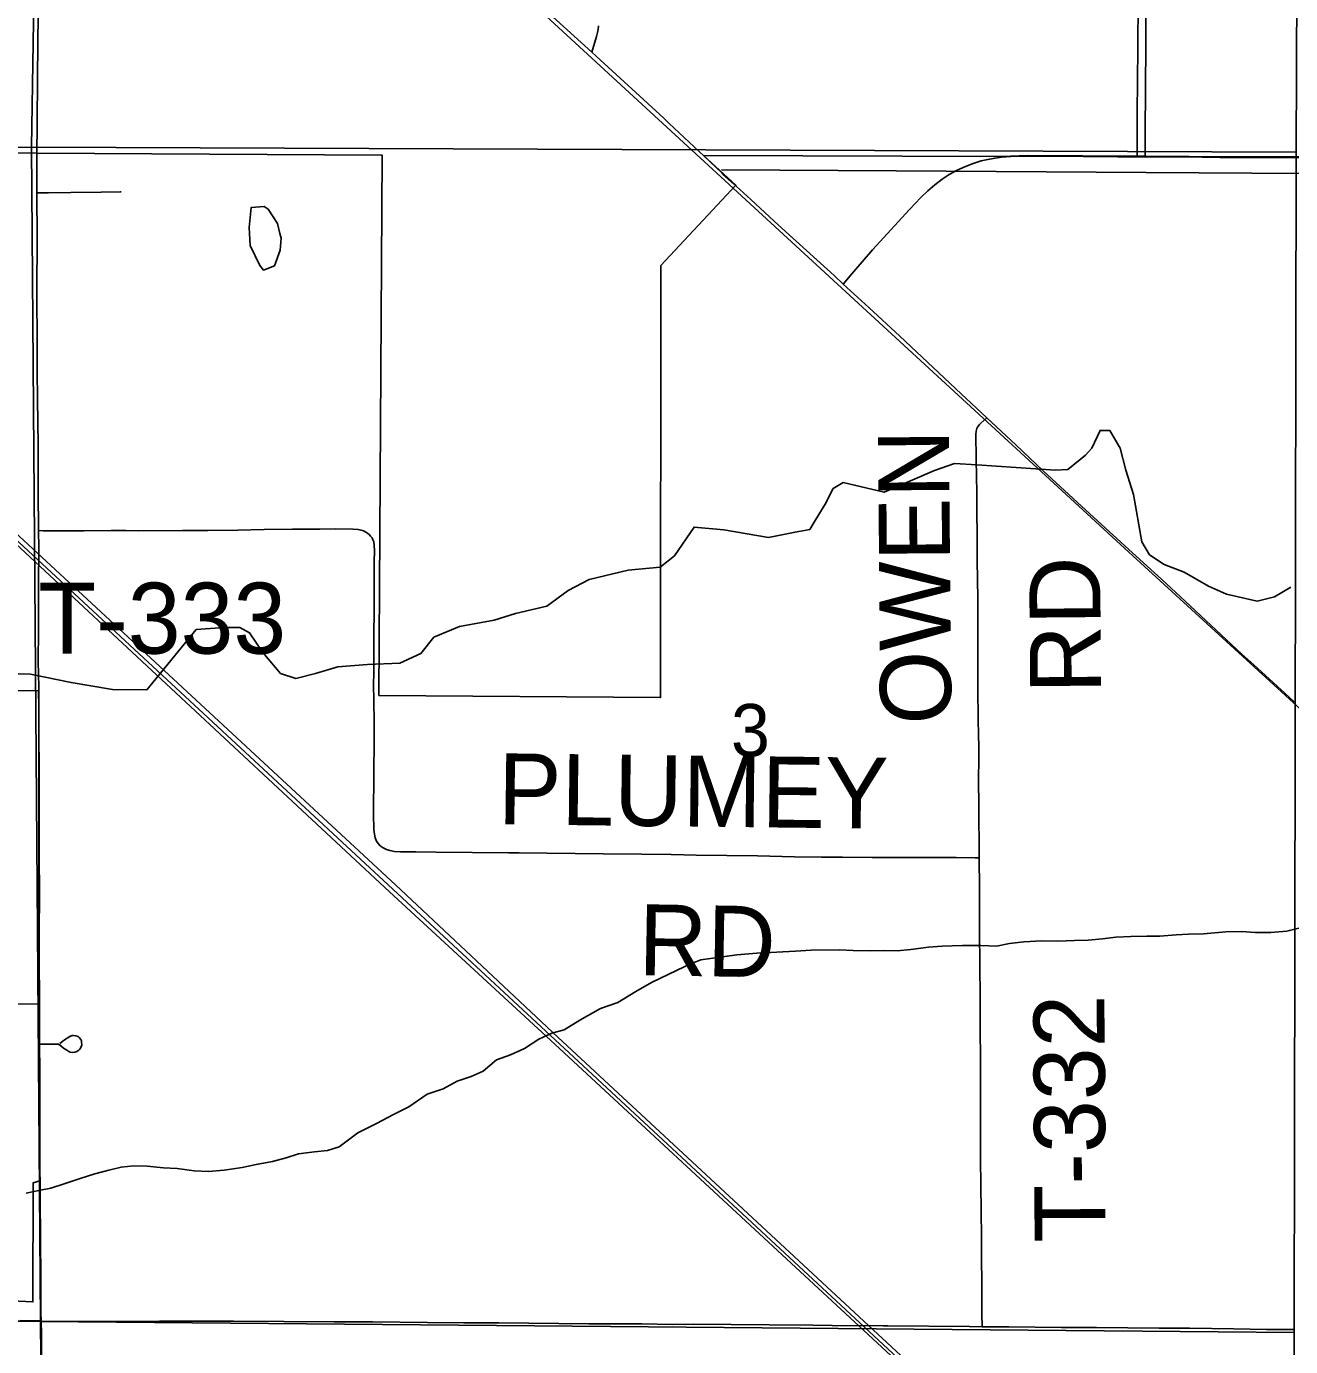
# Model space of a CAD drawing. Extents: x 0 to 40.2, y 0 to 22.
# Drawn here: x 5.744 to 6.757, y 15.297 to 16.354 of the extents above; entities that cross this region are included whole.
import ezdxf

# ---------------------------------------------------------------- set-up
doc = ezdxf.new("R2010")
doc.units = 0
for name, color, linetype in [('GM_X_City_Street', 7, 'Continuous'), ('GM_X_Corporation', 7, 'Continuous'), ('GM_X_County_Road_Text', 7, 'Continuous'), ('GM_X_Major_Lake', 7, 'Continuous'), ('GM_X_Major_River', 7, 'Continuous'), ('GM_X_Minor_Lake', 7, 'Continuous'), ('GM_X_Minor_Lake_Text', 7, 'Continuous'), ('GM_X_Rail_Line', 7, 'Continuous'), ('GM_X_Unincorporated_Location', 7, 'Continuous')]:
    doc.layers.add(name, color=color, linetype=linetype)

msp = doc.modelspace()

# ---------------------------------------------------------------- linework, layer by layer
at = {"layer": 'GM_X_Corporation'}
for points in [[(4.773, 17.2675), (5.7644, 17.2596), (5.7484, 16.2569), (4.7705, 16.2552)], [(5.7644, 17.2596), (6.765, 17.2565), (6.7611, 16.2529), (5.7484, 16.2569)], [(5.7484, 16.2569), (5.7558, 15.3168), (4.745, 15.3208), (4.7398, 16.2563), (4.7705, 16.2552)], [(6.7611, 16.2529), (6.7593, 15.308), (5.7558, 15.3168), (5.7484, 16.2569)], [(4.745, 15.3208), (5.7558, 15.3168), (5.7651, 14.3097), (4.749, 14.3145)], [(5.7558, 15.3168), (6.7593, 15.308), (6.7653, 14.3024), (5.7651, 14.3097)]]:
    msp.add_lwpolyline(points, close=True, dxfattribs=at)
for points in [[(5.6048, 16.2528), (5.7527, 16.2521), (6.0292, 16.2505), (6.0267, 15.818), (6.2521, 15.8162), (6.2524, 16.1621), (6.3124, 16.2264), (6.2866, 16.2502), (6.5251, 16.2494), (6.5465, 16.2503), (6.6335, 16.2496), (6.6399, 16.2496), (6.7112, 16.2492), (6.8181, 16.2493)], [(5.6162, 15.5696), (5.7547, 15.5709), (5.7548, 15.5771), (5.7545, 15.6044), (5.7544, 15.6274), (5.7545, 15.6603), (5.7544, 15.6896), (5.7545, 15.7232), (5.7545, 15.7487), (5.7543, 15.7978), (5.7543, 15.8121), (5.7542, 15.8179), (5.7542, 15.8217), (5.6015, 15.8223)], [(5.7395, 15.3176), (5.756, 15.3172), (5.7559, 15.3188), (5.7559, 15.3232), (5.7557, 15.3511), (5.7555, 15.3841), (5.7552, 15.4152), (5.7551, 15.4292), (5.7499, 15.4277), (5.7496, 15.3323), (5.6934, 15.3352)]]:
    msp.add_lwpolyline(points, dxfattribs=at)
at = {"layer": 'GM_X_Major_Lake'}
msp.add_line((6.2869, 16.2497), (6.2591, 16.2759), dxfattribs=at)
for points in [[(6.2007, 16.3297), (6.1971, 16.333), (6.1518, 16.374)], [(6.2591, 16.2759), (6.2547, 16.2801), (6.2007, 16.3297)], [(6.3126, 16.2258), (6.3108, 16.2276), (6.3021, 16.2354), (6.3014, 16.2361), (6.2869, 16.2497)], [(6.3983, 16.1473), (6.4053, 16.1556), (6.4217, 16.1747), (6.4515, 16.2071), (6.4604, 16.2165), (6.4662, 16.222), (6.4717, 16.2268), (6.4775, 16.2312), (6.4832, 16.2349), (6.4896, 16.2384), (6.4962, 16.2415), (6.5025, 16.2439), (6.5089, 16.2459), (6.5154, 16.2474), (6.5199, 16.2482), (6.5254, 16.2489)], [(6.5254, 16.2489), (6.5325, 16.2493), (6.5412, 16.2496), (6.5642, 16.2496), (6.5907, 16.2494), (6.6183, 16.2491), (6.6338, 16.2491), (6.6401, 16.249), (6.646, 16.2491), (6.6713, 16.2491), (6.7, 16.2487), (6.735, 16.2485), (6.7564, 16.2486)], [(6.7564, 16.2486), (6.7717, 16.2486)], [(6.4929, 16.0594), (6.4703, 16.0805), (6.4436, 16.1056), (6.4189, 16.1284), (6.3983, 16.1473), (6.391, 16.1541), (6.3551, 16.1867), (6.3432, 16.1977), (6.3244, 16.2149), (6.3126, 16.2258)], [(6.5365, 16.0185), (6.5133, 16.0403), (6.4929, 16.0594)], [(6.7595, 15.8128), (6.752, 15.8197), (6.7272, 15.8423), (6.7175, 15.8511), (6.672, 15.8934), (6.6534, 15.9108), (6.6239, 15.9376), (6.5891, 15.9696), (6.5585, 15.9977), (6.5365, 16.0185)]]:
    msp.add_lwpolyline(points, dxfattribs=at)
at = {"layer": 'GM_X_Major_River'}
for points in [[(4.9799, 17.4209), (5.3025, 17.1358), (5.9504, 16.5554), (6.6271, 15.9327), (7.157, 15.4476), (7.7681, 14.8787), (8.2449, 14.4419), (8.6184, 14.1)], [(4.1455, 17.415), (4.1542, 17.4069), (4.3224, 17.2484), (4.5126, 17.0764), (4.6277, 16.9694), (4.7733, 16.8366), (5.084, 16.5474), (5.609, 16.0605), (6.0377, 15.6628), (6.1678, 15.5423), (6.5654, 15.1729), (7.036, 14.7358), (7.4144, 14.3845), (7.7209, 14.1)], [(4.1471, 17.4167), (4.1558, 17.4086), (4.3239, 17.2501), (4.5142, 17.0781), (4.6293, 16.9711), (4.7748, 16.8383), (5.0856, 16.5491), (5.6113, 16.0632), (6.0399, 15.6663), (6.1698, 15.5443), (6.5669, 15.1758), (7.0383, 14.7375), (7.4155, 14.3872), (7.7237, 14.1)], [(4.7243, 16.8813), (4.7752, 16.8317), (5.0824, 16.5458), (5.6074, 16.0588), (6.0352, 15.6606), (6.1639, 15.542), (6.5637, 15.1714), (7.0334, 14.7344), (7.4114, 14.3836), (7.7174, 14.1)]]:
    msp.add_lwpolyline(points, dxfattribs=at)
at = {"layer": 'GM_X_Minor_Lake'}
for points in [[(7.7258, 16.2306), (7.4879, 16.2318), (7.3657, 16.2314), (7.2257, 16.231), (7.1107, 16.2325), (6.9163, 16.2345), (6.768, 16.2358), (6.6409, 16.2367), (6.4408, 16.238), (6.3009, 16.2388)], [(6.7567, 15.9047), (6.7437, 15.897), (6.7297, 15.8934), (6.7052, 15.8991), (6.6909, 15.9054), (6.6714, 15.9167), (6.6553, 15.9227), (6.6436, 15.9305), (6.6374, 15.9408), (6.6308, 15.9789), (6.6247, 15.9983), (6.62, 16.0158), (6.6119, 16.03), (6.604, 16.0301), (6.5973, 16.0158), (6.5923, 16.0102), (6.5781, 15.9987), (6.5683, 15.9984), (6.5052, 16.0025), (6.4874, 16.0035), (6.4714, 15.9981)], [(6.4714, 15.9981), (6.4311, 15.9806), (6.3983, 15.9883), (6.3903, 15.9835), (6.384, 15.9711), (6.3759, 15.9579), (6.3716, 15.9508), (6.3598, 15.9487), (6.3386, 15.9445), (6.3027, 15.9504)], [(6.3027, 15.9504), (6.2789, 15.9527), (6.2634, 15.9298), (6.2519, 15.9205), (6.2262, 15.9182), (6.195, 15.9108), (6.1782, 15.9019), (6.161, 15.8893), (6.136, 15.8836), (6.1188, 15.8782), (6.0911, 15.873), (6.0706, 15.8646), (6.0602, 15.8515), (6.0434, 15.8438), (6.0176, 15.8427), (5.9938, 15.8408)], [(5.5489, 15.8408), (5.6211, 15.8385), (5.699, 15.8364), (5.7478, 15.8349), (5.7802, 15.8283), (5.8134, 15.8228), (5.8409, 15.8225), (5.8804, 15.8707), (5.9029, 15.8722), (5.9152, 15.8724), (5.9231, 15.8681), (5.9338, 15.8524), (5.9479, 15.8355), (5.9601, 15.8315), (5.9759, 15.8354), (5.9938, 15.8408)], [(6.7641, 15.6318), (6.7535, 15.6293), (6.7406, 15.628), (6.7281, 15.6282), (6.7172, 15.6288), (6.7047, 15.6286), (6.6869, 15.627), (6.6748, 15.6268), (6.6649, 15.6262), (6.6517, 15.6253), (6.6415, 15.6251), (6.6286, 15.6249), (6.6165, 15.6243), (6.6059, 15.623), (6.5945, 15.622), (6.5835, 15.6218), (6.5703, 15.6213), (6.557, 15.6215), (6.543, 15.6206), (6.5316, 15.6193), (6.521, 15.6172), (6.5085, 15.6177), (6.4938, 15.6176), (6.4775, 15.6171), (6.4665, 15.6165), (6.4525, 15.6145), (6.4415, 15.6135), (6.4317, 15.6137), (6.42, 15.6135), (6.4063, 15.6137), (6.3954, 15.6143), (6.3727, 15.6139), (6.3602, 15.6133), (6.3499, 15.6127), (6.3401, 15.6121), (6.3291, 15.6115), (6.3132, 15.6103), (6.2844, 15.6062), (6.2749, 15.6025), (6.2654, 15.5981), (6.2448, 15.5882), (6.2322, 15.5808), (6.218, 15.572), (6.204, 15.5673), (6.1875, 15.558), (6.1749, 15.5503), (6.1651, 15.5474), (6.1548, 15.5426), (6.1433, 15.5352), (6.1319, 15.5301), (6.1208, 15.5261), (6.1101, 15.5172), (6.1006, 15.5128)], [(6.1006, 15.5128), (6.0892, 15.5092), (6.0781, 15.5029), (6.0652, 15.4986), (6.0506, 15.4885), (6.0384, 15.4823), (6.0247, 15.4753), (6.0098, 15.4676), (5.9949, 15.4564), (5.9854, 15.4536), (5.9751, 15.4526), (5.9623, 15.4509), (5.9524, 15.4476), (5.9414, 15.4448), (5.9285, 15.4423), (5.9171, 15.4399), (5.9027, 15.4378), (5.8902, 15.4369), (5.8788, 15.4374), (5.8652, 15.4392), (5.8543, 15.4397), (5.841, 15.4411), (5.8304, 15.4413), (5.8202, 15.4403), (5.8103, 15.4378), (5.7993, 15.4349), (5.7875, 15.4313), (5.7746, 15.427), (5.764, 15.4234), (5.7545, 15.4216), (5.7442, 15.4195)]]:
    msp.add_lwpolyline(points, dxfattribs=at)
at = {"layer": 'GM_X_Minor_Lake_Text'}
msp.add_line((5.9485, 16.1841), (5.9474, 16.1879), dxfattribs=at)
msp.add_lwpolyline([(5.9474, 16.1879), (5.9455, 16.1959), (5.938, 16.2073), (5.9347, 16.2093), (5.9244, 16.2086), (5.9228, 16.1927), (5.9235, 16.1782), (5.9313, 16.1622), (5.9343, 16.1584), (5.943, 16.1618), (5.9477, 16.1743), (5.9485, 16.1841)], dxfattribs=at)
at = {"layer": 'GM_X_Rail_Line'}
for points in [[(5.7529, 16.2516), (5.753, 16.2748), (5.7532, 16.3133), (5.7539, 16.3643), (5.7544, 16.4047), (5.7556, 16.4861), (5.756, 16.5352), (5.756, 16.5551), (5.7561, 16.5588), (5.7564, 16.5731), (5.7567, 16.5961), (5.757, 16.6029), (5.7578, 16.6557), (5.7578, 16.664), (5.7579, 16.6728), (5.758, 16.6792), (5.7583, 16.6963), (5.7588, 16.7149), (5.7591, 16.731)], [(5.7529, 16.2204), (5.7528, 16.2415), (5.7529, 16.2516)], [(5.7541, 15.9499), (5.7538, 15.9812), (5.7539, 16.0184), (5.7533, 16.0551), (5.7531, 16.0775), (5.7531, 16.0999), (5.7528, 16.1396), (5.753, 16.1863), (5.7529, 16.218), (5.7529, 16.2204)], [(5.7529, 16.2204), (5.755, 16.2204), (5.7622, 16.2204), (5.7801, 16.2205), (5.8042, 16.221), (5.8196, 16.2211), (5.8203, 16.2211)], [(6.5071, 15.688), (6.5071, 15.6962), (6.507, 15.7224), (6.5067, 15.7573), (6.5068, 15.7604), (6.5068, 15.7672), (6.5068, 15.7753), (6.5067, 15.7882), (6.5065, 15.7969), (6.5064, 15.8065), (6.5062, 15.816), (6.5061, 15.8261), (6.5061, 15.835), (6.5061, 15.8452), (6.5061, 15.8553), (6.5061, 15.8714), (6.5061, 15.8764), (6.506, 15.8956), (6.5056, 15.9259), (6.5055, 15.9344), (6.5055, 15.9359), (6.5052, 15.9755), (6.5052, 15.9809), (6.505, 15.9926), (6.5048, 16.0076), (6.5046, 16.0268), (6.5048, 16.0294), (6.505, 16.0306), (6.5054, 16.0317), (6.5059, 16.0326), (6.5066, 16.0337), (6.5075, 16.0348), (6.5086, 16.0358), (6.5133, 16.0403)], [(5.7541, 15.9499), (5.7579, 15.9498), (5.7905, 15.9497), (5.8122, 15.9499), (5.824, 15.95), (5.8338, 15.9498), (5.8695, 15.9499), (5.8897, 15.9501), (5.9136, 15.9503), (5.9348, 15.9508), (5.9574, 15.9511), (5.9692, 15.951), (5.9793, 15.9511), (5.992, 15.9512), (6.006, 15.9511), (6.0098, 15.9508), (6.0124, 15.9503), (6.0143, 15.9497), (6.0166, 15.9485), (6.0178, 15.9477), (6.0189, 15.9467), (6.0199, 15.9455), (6.0212, 15.944), (6.0219, 15.9425), (6.0225, 15.941)], [(5.7544, 15.8212), (5.7543, 15.8249), (5.7539, 15.8452), (5.7541, 15.8701), (5.7542, 15.8788), (5.7542, 15.8819), (5.7541, 15.8906), (5.754, 15.9117), (5.754, 15.9173), (5.7543, 15.9253), (5.7543, 15.9377), (5.7541, 15.9483), (5.7541, 15.9499)], [(6.0225, 15.941), (6.0229, 15.938), (6.023, 15.9341), (6.0229, 15.9247), (6.0229, 15.9166), (6.0228, 15.9085), (6.0228, 15.8868), (6.0225, 15.8651), (6.0225, 15.8402), (6.0224, 15.8222), (6.0225, 15.8183), (6.0225, 15.8173)], [(5.755, 15.5695), (5.755, 15.5703), (5.755, 15.5765), (5.7547, 15.6038), (5.7546, 15.6268), (5.7548, 15.6598), (5.7546, 15.689), (5.7547, 15.7226), (5.7547, 15.7481), (5.7545, 15.7972), (5.7545, 15.8115), (5.7544, 15.8174), (5.7544, 15.8212)], [(6.0225, 15.8173), (6.0229, 15.7929), (6.0228, 15.7737), (6.0227, 15.7639), (6.0227, 15.7465), (6.0223, 15.7316), (6.0223, 15.723), (6.0227, 15.7106), (6.023, 15.7069), (6.0237, 15.704), (6.0248, 15.7013), (6.0261, 15.6993), (6.0276, 15.6976), (6.03, 15.6959), (6.0326, 15.6946), (6.0354, 15.6937), (6.039, 15.693), (6.0439, 15.6927), (6.0563, 15.6926), (6.0724, 15.6925), (6.1303, 15.692), (6.139, 15.692), (6.2061, 15.6911), (6.2372, 15.6909), (6.2607, 15.6905), (6.2806, 15.6901), (6.3297, 15.6894), (6.3594, 15.6888), (6.381, 15.6884), (6.3978, 15.6884), (6.4215, 15.6882), (6.4444, 15.6882), (6.4694, 15.6881), (6.4887, 15.6881), (6.504, 15.688), (6.5071, 15.688)], [(6.5095, 15.3125), (6.5095, 15.3151), (6.5093, 15.3202), (6.5093, 15.3315), (6.5092, 15.3456), (6.5091, 15.3693), (6.5091, 15.3862), (6.5088, 15.4028), (6.5087, 15.409), (6.5086, 15.422), (6.5082, 15.4505), (6.5083, 15.4555), (6.5082, 15.4592), (6.5082, 15.4648), (6.5083, 15.4717), (6.5082, 15.476), (6.5082, 15.4785), (6.5082, 15.4951), (6.5083, 15.5023), (6.5083, 15.508), (6.5082, 15.5296), (6.5081, 15.5478), (6.5081, 15.5539), (6.508, 15.5654), (6.508, 15.5722), (6.508, 15.5806), (6.5078, 15.5978), (6.5074, 15.6335), (6.5075, 15.6535), (6.5074, 15.6658), (6.5071, 15.6859), (6.5071, 15.688)], [(5.755, 15.5387), (5.755, 15.5581), (5.755, 15.5669), (5.755, 15.5695)], [(5.755, 15.5387), (5.7614, 15.5388), (5.7677, 15.5388), (5.7701, 15.5388), (5.772, 15.5375), (5.7741, 15.5356), (5.7767, 15.5338), (5.7783, 15.5329), (5.7795, 15.5324), (5.7813, 15.5321), (5.7832, 15.5323), (5.7849, 15.5329), (5.7865, 15.5339), (5.7873, 15.5348), (5.7882, 15.5365), (5.7887, 15.5383), (5.7886, 15.5402), (5.7884, 15.5414), (5.7879, 15.5425), (5.7867, 15.544), (5.7858, 15.5448), (5.7841, 15.5455), (5.7822, 15.5457), (5.781, 15.5456), (5.7793, 15.5449), (5.7771, 15.5436), (5.7748, 15.5423), (5.7735, 15.541), (5.7713, 15.5393)], [(5.7554, 15.4286), (5.7553, 15.4364), (5.7553, 15.4501), (5.7552, 15.465), (5.7551, 15.4818), (5.7551, 15.5042), (5.7552, 15.5147), (5.7551, 15.5203), (5.755, 15.5358), (5.755, 15.5387)], [(5.7562, 15.3167), (5.7562, 15.3182), (5.7561, 15.3226), (5.7559, 15.3506), (5.7557, 15.3835), (5.7555, 15.4146), (5.7554, 15.4286)], [(5.6728, 15.3179), (5.7037, 15.3177), (5.7397, 15.317), (5.7562, 15.3167)], [(5.7562, 15.3167), (5.8168, 15.3166), (5.851, 15.3169), (5.8941, 15.3169)], [(5.7578, 14.8912), (5.7578, 14.8993), (5.7575, 14.926), (5.7576, 14.9615), (5.7575, 15.0056), (5.7574, 15.0317), (5.7572, 15.0529), (5.7573, 15.0709), (5.7569, 15.1026), (5.7569, 15.1492), (5.7567, 15.1866), (5.7567, 15.2531), (5.7565, 15.2941), (5.7564, 15.3071), (5.7562, 15.3167)], [(5.8941, 15.3169), (5.9101, 15.3169), (5.9909, 15.3164), (6.0214, 15.3164), (6.0655, 15.316), (6.0947, 15.3157), (6.1227, 15.3155), (6.1948, 15.3149), (6.2371, 15.3148), (6.262, 15.3144), (6.2781, 15.3145), (6.3391, 15.3139), (6.3739, 15.3137), (6.3894, 15.3135), (6.4304, 15.3132), (6.4341, 15.3132), (6.4994, 15.3126), (6.5095, 15.3125)], [(6.5095, 15.3125), (6.5309, 15.3124), (6.5732, 15.312), (6.6012, 15.312), (6.6514, 15.3113), (6.6756, 15.3113), (6.7111, 15.3107), (6.7372, 15.3103), (6.7599, 15.3104)]]:
    msp.add_lwpolyline(points, dxfattribs=at)
at = {"layer": 'GM_X_Unincorporated_Location'}
for points in [[(6.6338, 16.2491), (6.6338, 16.2555), (6.6338, 16.2675), (6.6338, 16.2873), (6.6339, 16.3072), (6.6345, 16.3711), (6.6348, 16.3879), (6.6352, 16.4488), (6.6358, 16.4848), (6.6359, 16.4932), (6.6359, 16.4945), (6.6361, 16.4963), (6.6364, 16.4975), (6.637, 16.4985), (6.6377, 16.4994), (6.6389, 16.5003)], [(6.6401, 16.249), (6.6401, 16.2655), (6.6404, 16.3068), (6.6406, 16.336), (6.6406, 16.3547), (6.6409, 16.3846), (6.6412, 16.4039), (6.6412, 16.4331), (6.6416, 16.4568), (6.6418, 16.4847), (6.6418, 16.4937), (6.6418, 16.4957), (6.6415, 16.4974), (6.6409, 16.4986), (6.6403, 16.4993), (6.6389, 16.5003)], [(6.1971, 16.333), (6.2008, 16.3455), (6.2017, 16.3486), (6.2022, 16.3511), (6.2024, 16.354)]]:
    msp.add_lwpolyline(points, dxfattribs=at)

# ---------------------------------------------------------------- texts
at = {"layer": 'GM_X_City_Street'}
msp.add_text('3', height=0.0419, rotation=0, dxfattribs=at).set_placement((6.3085, 15.7692))
at = {"layer": 'GM_X_County_Road_Text'}
for s, rotation, p in [('OWEN', 90.4592, (6.4849, 15.7948)), ('RD', 90.4959, (6.6049, 15.8196)), ('T-333', 0, (5.7539, 15.8514)), ('PLUMEY', 359.3338, (6.1217, 15.7148)), ('RD', 359.0237, (6.2341, 15.594)), ('T-332', 90.278, (6.6084, 15.38))]:
    msp.add_text(s, height=0.05682, rotation=rotation, dxfattribs=at).set_placement(p)

doc.saveas('drawing.dxf')
